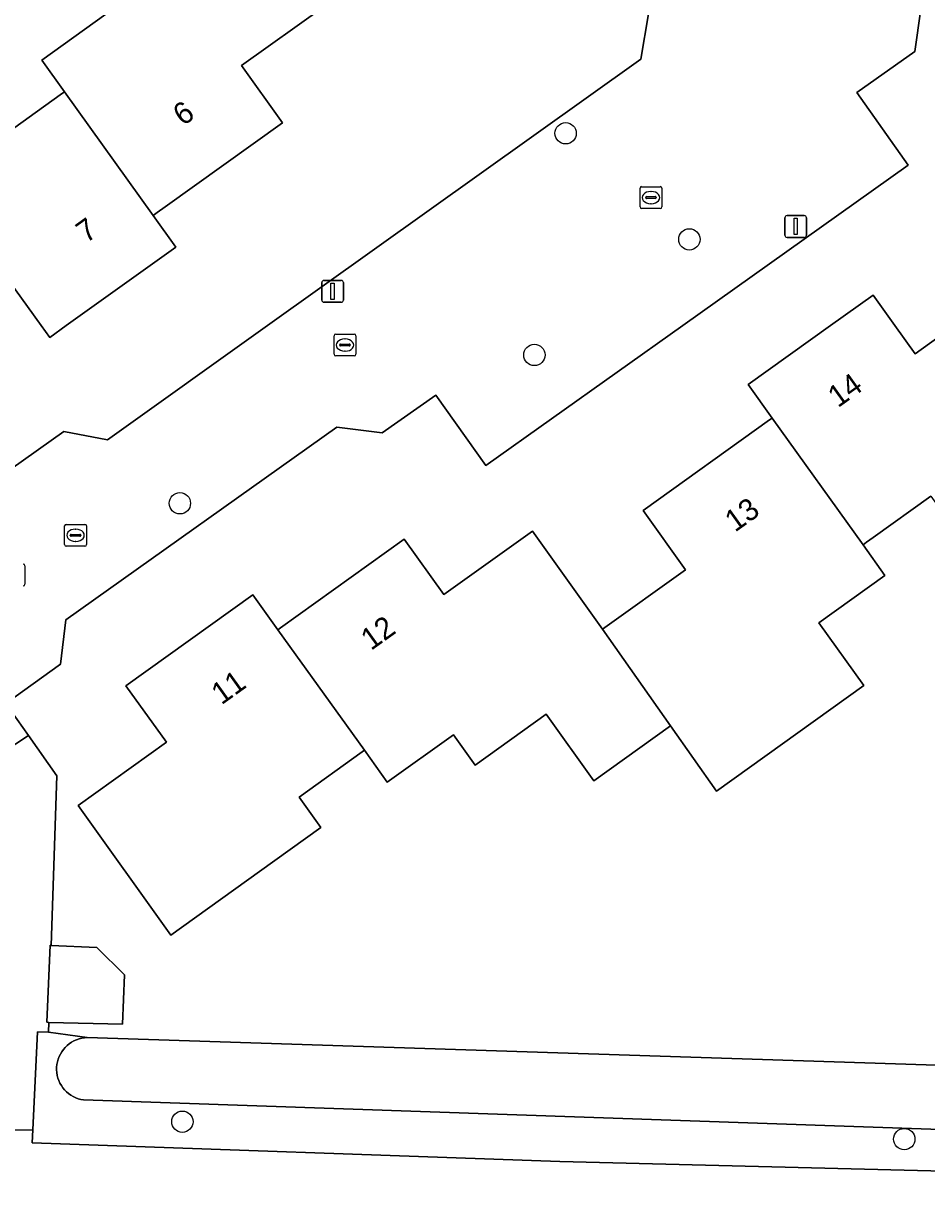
# Model space of a CAD drawing. Extents: x 158455 to 159797, y 387218 to 388672.
# Drawn here: x 159236.8 to 159278.2, y 387710.4 to 387763.8 of the extents above; entities that cross this region are included whole.
import ezdxf

# ---------------------------------------------------------------- set-up
doc = ezdxf.new("R2010")
doc.units = 0
for name, color, linetype in [('IMGEO_Boom', 7, 'Continuous'), ('IMGEO_Erf', 7, 'Continuous'), ('IMGEO_Groenvoorziening', 7, 'Continuous'), ('IMGEO_Kolk', 7, 'Continuous'), ('IMGEO_Lichtmast', 7, 'Continuous'), ('IMGEO_Pand', 7, 'Continuous'), ('IMGEO_Pand_nummerreeks', 7, 'Continuous'), ('IMGEO_Rijbaan_lokaal_open', 7, 'Continuous'), ('IMGEO_Rioolput', 7, 'Continuous'), ('IMGEO_Voetpad_halfverhard', 7, 'Continuous'), ('IMGEO_Voetpad_open', 7, 'Continuous'), ('IMGEO_Waterloop', 7, 'Continuous')]:
    doc.layers.add(name, color=color, linetype=linetype)

msp = doc.modelspace()

# ---------------------------------------------------------------- linework, layer by layer
at = {"layer": 'IMGEO_Boom'}
for centre in [(159261.608, 387758.813), (159267.278, 387753.948), (159260.177, 387748.653), (159243.927, 387741.855), (159244.041, 387713.516), (159277.129, 387712.716)]:
    msp.add_circle(centre, 0.489, dxfattribs=at)
at = {"layer": 'IMGEO_Erf'}
for points in [[(159219.866, 387766.077), (159225.4, 387758.477), (159225.842, 387757.87), (159227.788, 387755.197), (159234.513, 387760.012), (159235.582, 387758.518), (159238.444, 387760.567), (159238.638, 387760.706), (159237.594, 387762.164), (159240.534, 387764.269)], [(159250.519, 387764.612), (159246.754, 387761.916), (159248.635, 387759.288), (159243.252, 387755.433), (159242.894, 387755.177), (159242.699, 387755.037), (159243.735, 387753.59), (159238.722, 387750), (159237.962, 387749.456), (159237.572, 387750), (159236.047, 387752.13), (159235.872, 387752.374), (159234.896, 387751.676), (159235.071, 387751.431), (159233.071, 387750), (159232.039, 387749.261), (159236.184, 387743.412), (159238.603, 387745.147), (159240.605, 387744.76), (159247.948, 387750), (159265.053, 387762.206), (159265.409, 387764.288)], [(159277.893, 387764.497), (159277.605, 387762.555), (159274.948, 387760.678), (159277.299, 387757.343), (159266.972, 387750), (159257.945, 387743.581), (159255.655, 387746.817), (159253.197, 387745.09), (159251.126, 387745.348), (159238.707, 387736.519), (159238.451, 387734.477), (159235.953, 387732.682), (159236.986, 387731.212), (159238.284, 387729.366), (159238.03, 387721.596), (159240.126, 387721.505), (159241.394, 387720.245), (159241.296, 387717.992), (159237.915, 387718.068), (159237.9, 387717.615), (159239.681, 387717.367), (159366.763, 387713.237)], [(159278.344, 387742.177), (159275.701, 387740.283), (159275.402, 387740.069), (159275.24, 387739.953), (159276.243, 387738.553), (159273.209, 387736.38), (159275.27, 387733.502), (159268.522, 387728.668), (159266.418, 387731.657), (159262.899, 387729.137), (159260.716, 387732.185), (159257.468, 387729.858), (159256.47, 387731.25), (159253.434, 387729.075), (159252.386, 387730.534), (159252.287, 387730.463), (159249.394, 387728.391), (159250.394, 387726.995), (159247.581, 387724.981), (159243.516, 387722.069), (159239.265, 387728.004), (159243.313, 387730.904), (159241.458, 387733.492), (159247.273, 387737.658), (159248.419, 387736.061), (159248.541, 387736.148), (159254.213, 387740.211), (159256.029, 387737.676), (159260.082, 387740.579), (159263.303, 387736.081), (159267.105, 387738.805), (159265.159, 387741.522), (159270.956, 387745.675), (159271.077, 387745.762), (159269.977, 387747.297), (159273.75, 387750), (159275.697, 387751.395), (159276.697, 387750), (159277.626, 387748.703), (159279.437, 387750)]]:
    msp.add_lwpolyline(points, dxfattribs=at)
at = {"layer": 'IMGEO_Groenvoorziening'}
msp.add_lwpolyline([(159368.812, 387710.04), (159239.517, 387714.512), (159239.393, 387714.535), (159239.272, 387714.568), (159239.154, 387714.612), (159239.041, 387714.666), (159238.932, 387714.73), (159238.83, 387714.803), (159238.734, 387714.884), (159238.646, 387714.974), (159238.566, 387715.071), (159238.495, 387715.175), (159238.433, 387715.285), (159238.382, 387715.399), (159238.34, 387715.518), (159238.309, 387715.64), (159238.289, 387715.764), (159238.279, 387715.889), (159238.281, 387716.015), (159238.294, 387716.14), (159238.317, 387716.264), (159238.352, 387716.385), (159238.397, 387716.502), (159238.451, 387716.616), (159238.516, 387716.723), (159238.59, 387716.825), (159238.672, 387716.92), (159238.763, 387717.008), (159238.861, 387717.087), (159238.965, 387717.157), (159239.075, 387717.218), (159239.19, 387717.269), (159239.309, 387717.309), (159239.431, 387717.339), (159239.556, 387717.359), (159239.681, 387717.367), (159237.9, 387717.615), (159237.4, 387717.632), (159237.189, 387713.141), (159237.161, 387712.542), (159261.348, 387711.686), (159337.222, 387709.784)], dxfattribs=at)
at = {"layer": 'IMGEO_Kolk'}
for p, q in [((159265.017, 387755.438), (159265.017, 387756.29)), ((159265.092, 387756.364), (159265.944, 387756.364)), ((159265.505, 387756.144), (159265.53, 387756.144)), ((159266.018, 387756.29), (159266.018, 387755.438)), ((159265.276, 387755.858), (159265.276, 387755.87)), ((159265.714, 387755.821), (159265.316, 387755.821)), ((159265.319, 387755.907), (159265.717, 387755.907)), ((159265.528, 387755.584), (159265.503, 387755.584)), ((159265.76, 387755.87), (159265.76, 387755.858)), ((159265.944, 387755.364), (159265.092, 387755.364)), ((159251.068, 387749.607), (159251.92, 387749.607)), ((159250.993, 387748.681), (159250.993, 387749.533)), ((159251.252, 387749.101), (159251.252, 387749.113)), ((159251.69, 387749.064), (159251.292, 387749.064)), ((159251.295, 387749.15), (159251.693, 387749.15)), ((159251.481, 387749.387), (159251.506, 387749.387)), ((159251.736, 387749.113), (159251.736, 387749.101)), ((159251.994, 387749.533), (159251.994, 387748.681)), ((159251.92, 387748.607), (159251.068, 387748.607)), ((159251.504, 387748.827), (159251.479, 387748.827)), ((159238.647, 387739.962), (159238.647, 387740.814)), ((159238.722, 387740.888), (159239.574, 387740.888)), ((159239.135, 387740.668), (159239.16, 387740.668)), ((159239.648, 387740.814), (159239.648, 387739.962)), ((159238.906, 387740.382), (159238.906, 387740.394)), ((159239.344, 387740.345), (159238.946, 387740.345)), ((159238.949, 387740.431), (159239.347, 387740.431)), ((159239.158, 387740.108), (159239.133, 387740.108)), ((159239.39, 387740.394), (159239.39, 387740.382)), ((159239.574, 387739.888), (159238.722, 387739.888))]:
    msp.add_line(p, q, dxfattribs=at)
for points in [[(159265.017, 387755.438), (159265.017, 387756.29)], [(159265.092, 387756.364), (159265.944, 387756.364)], [(159266.018, 387756.29), (159266.018, 387755.438)], [(159265.944, 387755.364), (159265.092, 387755.364)], [(159251.068, 387749.607), (159251.92, 387749.607)], [(159250.993, 387748.681), (159250.993, 387749.533)], [(159251.994, 387749.533), (159251.994, 387748.681)], [(159251.92, 387748.607), (159251.068, 387748.607)], [(159238.647, 387739.962), (159238.647, 387740.814)], [(159238.722, 387740.888), (159239.574, 387740.888)], [(159239.648, 387740.814), (159239.648, 387739.962)], [(159239.574, 387739.888), (159238.722, 387739.888)]]:
    msp.add_lwpolyline(points, dxfattribs=at)
for centre, radius, start, end in [((159265.094, 387756.288), 0.0765, 91.552, 178.448), ((159265.094, 387756.288), 0.0765, 91.552, 178.448), ((159265.942, 387756.288), 0.0765, 1.552, 88.448), ((159265.942, 387756.288), 0.0765, 1.552, 88.448), ((159265.094, 387755.44), 0.0765, 181.552, 268.448), ((159265.094, 387755.44), 0.0765, 181.552, 268.448), ((159265.316, 387755.867), 0.0403, 85.8775, 175.7526), ((159265.313, 387755.857), 0.0366, 178.938, 274.7102), ((159265.717, 387755.864), 0.043, 264.8664, 352.4533), ((159265.721, 387755.869), 0.0386, 1.7309, 96.639), ((159265.942, 387755.44), 0.0765, 271.552, 358.448), ((159265.942, 387755.44), 0.0765, 271.552, 358.448), ((159251.07, 387749.531), 0.0765, 91.552, 178.448), ((159251.07, 387749.531), 0.0765, 91.552, 178.448), ((159251.918, 387749.531), 0.0765, 1.552, 88.448), ((159251.918, 387749.531), 0.0765, 1.552, 88.448), ((159251.292, 387749.11), 0.0403, 85.8775, 175.7526), ((159251.289, 387749.1), 0.0366, 178.938, 274.7102), ((159251.693, 387749.107), 0.043, 264.8664, 352.4533), ((159251.697, 387749.112), 0.0386, 1.7309, 96.639), ((159251.07, 387748.683), 0.0765, 181.552, 268.448), ((159251.07, 387748.683), 0.0765, 181.552, 268.448), ((159251.918, 387748.683), 0.0765, 271.552, 358.448), ((159251.918, 387748.683), 0.0765, 271.552, 358.448), ((159238.724, 387740.812), 0.0765, 91.552, 178.448), ((159238.724, 387740.812), 0.0765, 91.552, 178.448), ((159239.572, 387740.812), 0.0765, 1.552, 88.448), ((159239.572, 387740.812), 0.0765, 1.552, 88.448), ((159238.724, 387739.964), 0.0765, 181.552, 268.448), ((159238.724, 387739.964), 0.0765, 181.552, 268.448), ((159238.946, 387740.391), 0.0403, 85.8775, 175.7526), ((159238.943, 387740.381), 0.0366, 178.938, 274.7102), ((159239.347, 387740.388), 0.043, 264.8664, 352.4533), ((159239.351, 387740.393), 0.0386, 1.7309, 96.639), ((159239.572, 387739.964), 0.0765, 271.552, 358.448), ((159239.572, 387739.964), 0.0765, 271.552, 358.448)]:
    msp.add_arc(centre, radius, start, end, dxfattribs=at)
for centre, major_axis, ratio, start_param, end_param in [((159265.504, 387755.864), (-0.387, 0.002), 0.722429, 4.712389, 7.853982), ((159265.529, 387755.864), (-0.39, 0.002), 0.717154, 1.570796, 4.712389), ((159251.48, 387749.107), (-0.387, 0.002), 0.722429, 4.712389, 7.853982), ((159251.505, 387749.107), (-0.39, 0.002), 0.717154, 1.570796, 4.712389), ((159239.134, 387740.388), (-0.387, 0.002), 0.722429, 4.712389, 7.853982), ((159239.159, 387740.388), (-0.39, 0.002), 0.717154, 1.570796, 4.712389)]:
    msp.add_ellipse(centre, major_axis=major_axis, ratio=ratio, start_param=start_param, end_param=end_param, dxfattribs=at)
at = {"layer": 'IMGEO_Lichtmast'}
for p, q in [((159271.654, 387754.142), (159271.654, 387754.942)), ((159271.654, 387754.942), (159271.654, 387754.142)), ((159271.754, 387755.042), (159272.544, 387755.042)), ((159272.544, 387755.042), (159271.754, 387755.042)), ((159272.644, 387754.942), (159272.644, 387754.142)), ((159272.644, 387754.142), (159272.644, 387754.942)), ((159272.544, 387754.042), (159271.754, 387754.042)), ((159271.754, 387754.042), (159272.544, 387754.042)), ((159250.431, 387751.168), (159250.431, 387751.968)), ((159250.431, 387751.968), (159250.431, 387751.168)), ((159250.531, 387752.068), (159251.321, 387752.068)), ((159251.321, 387752.068), (159250.531, 387752.068)), ((159251.421, 387751.968), (159251.421, 387751.168)), ((159251.421, 387751.168), (159251.421, 387751.968)), ((159251.321, 387751.068), (159250.531, 387751.068)), ((159250.531, 387751.068), (159251.321, 387751.068))]:
    msp.add_line(p, q, dxfattribs=at)
for points in [[(159272.074, 387754.917), (159272.224, 387754.917), (159272.224, 387754.167), (159272.074, 387754.167), (159272.074, 387754.917)], [(159250.851, 387751.943), (159251.001, 387751.943), (159251.001, 387751.193), (159250.851, 387751.193), (159250.851, 387751.943)]]:
    msp.add_lwpolyline(points, dxfattribs=at)
for centre, start, end in [((159271.754, 387754.942), 90, 180), ((159271.754, 387754.942), 90, 180), ((159272.544, 387754.942), 0, 90), ((159272.544, 387754.942), 360, 90), ((159271.754, 387754.142), 180, 270), ((159271.754, 387754.142), 180, 270), ((159272.544, 387754.142), 270, 0), ((159272.544, 387754.142), 270, 0), ((159250.531, 387751.968), 90, 180), ((159250.531, 387751.968), 90, 180), ((159251.321, 387751.968), 0, 90), ((159251.321, 387751.968), 360, 90), ((159250.531, 387751.168), 180, 270), ((159250.531, 387751.168), 180, 270), ((159251.321, 387751.168), 270, 0), ((159251.321, 387751.168), 270, 0)]:
    msp.add_arc(centre, 0.1, start, end, dxfattribs=at)
at = {"layer": 'IMGEO_Pand'}
for points in [[(159250.519, 387764.612), (159246.217, 387770.619), (159243.702, 387774.131), (159240.092, 387771.546), (159242.607, 387768.034), (159239.455, 387765.777), (159240.534, 387764.269), (159237.594, 387762.164), (159238.638, 387760.706), (159242.699, 387755.037), (159242.894, 387755.177), (159243.252, 387755.433), (159248.635, 387759.288), (159246.754, 387761.916)], [(159238.638, 387760.706), (159238.444, 387760.567), (159235.582, 387758.518), (159234.513, 387760.012), (159227.788, 387755.197), (159231.51, 387750), (159232.039, 387749.261), (159233.071, 387750), (159235.071, 387751.431), (159234.896, 387751.676), (159235.872, 387752.374), (159236.047, 387752.13), (159237.572, 387750), (159237.962, 387749.456), (159238.722, 387750), (159243.735, 387753.59), (159242.699, 387755.037)], [(159282.735, 387750), (159281.618, 387751.562), (159281.499, 387751.477), (159279.437, 387750), (159277.626, 387748.703), (159276.697, 387750), (159275.697, 387751.395), (159273.75, 387750), (159269.977, 387747.297), (159271.077, 387745.762), (159275.24, 387739.953), (159275.402, 387740.069), (159275.701, 387740.283), (159278.344, 387742.177), (159279.38, 387740.73), (159285.986, 387745.462)], [(159276.243, 387738.553), (159275.24, 387739.953), (159271.077, 387745.762), (159270.956, 387745.675), (159265.159, 387741.522), (159267.105, 387738.805), (159263.303, 387736.081), (159266.418, 387731.657), (159268.522, 387728.668), (159275.27, 387733.502), (159273.209, 387736.38)], [(159263.303, 387736.081), (159260.082, 387740.579), (159256.029, 387737.676), (159254.213, 387740.211), (159248.541, 387736.148), (159248.419, 387736.061), (159252.386, 387730.534), (159253.434, 387729.075), (159256.47, 387731.25), (159257.468, 387729.858), (159260.716, 387732.185), (159262.899, 387729.137), (159266.418, 387731.657)], [(159252.287, 387730.463), (159252.386, 387730.534), (159248.419, 387736.061), (159247.273, 387737.658), (159241.458, 387733.492), (159243.313, 387730.904), (159239.265, 387728.004), (159243.516, 387722.069), (159247.581, 387724.981), (159250.394, 387726.995), (159249.394, 387728.391)], [(159238.03, 387721.596), (159237.985, 387721.598), (159237.832, 387718.07), (159237.915, 387718.068), (159241.296, 387717.992), (159241.394, 387720.245), (159240.126, 387721.505)]]:
    msp.add_lwpolyline(points, close=True, dxfattribs=at)
at = {"layer": 'IMGEO_Rijbaan_lokaal_open'}
for points in [[(159235.227, 387730.066), (159236.986, 387731.212), (159235.953, 387732.682), (159238.451, 387734.477), (159238.707, 387736.519), (159251.126, 387745.348), (159253.197, 387745.09), (159255.655, 387746.817), (159257.945, 387743.581), (159266.972, 387750), (159277.299, 387757.343), (159274.948, 387760.678), (159277.605, 387762.555), (159277.893, 387764.497)], [(159265.409, 387764.288), (159265.053, 387762.206), (159247.948, 387750), (159240.605, 387744.76), (159238.603, 387745.147), (159236.184, 387743.412)]]:
    msp.add_lwpolyline(points, dxfattribs=at)
at = {"layer": 'IMGEO_Rioolput'}
msp.add_line((159236.826, 387738.993), (159236.826, 387738.141), dxfattribs=at)
msp.add_lwpolyline([(159236.826, 387738.993), (159236.826, 387738.141)], dxfattribs=at)
for centre, start, end in [((159236.75, 387738.991), 1.552, 88.448), ((159236.75, 387738.991), 1.552, 88.448), ((159236.75, 387738.143), 271.552, 358.448), ((159236.75, 387738.143), 271.552, 358.448)]:
    msp.add_arc(centre, 0.0765, start, end, dxfattribs=at)
at = {"layer": 'IMGEO_Voetpad_halfverhard'}
msp.add_lwpolyline([(159440.368, 387706.497), (159440.403, 387707.122), (159439.155, 387707.164), (159439.115, 387706.535), (159433.346, 387706.713), (159386.156, 387708.167), (159372.279, 387708.595), (159372.194, 387709.441), (159371.015, 387709.344), (159371.1, 387708.633), (159337.222, 387709.784), (159261.348, 387711.686), (159237.161, 387712.542), (159237.189, 387713.141), (159235.969, 387713.133), (159235.947, 387712.585), (159217.158, 387713.181), (159215.858, 387713.235), (159215.088, 387713.348), (159209.072, 387716.044), (159214.062, 387706.489), (159214.378, 387707.16), (159215.755, 387708.691), (159216.346, 387709.347)], dxfattribs=at)
at = {"layer": 'IMGEO_Voetpad_open'}
msp.add_lwpolyline([(159238.284, 387729.366), (159236.986, 387731.212), (159235.227, 387730.066), (159236.179, 387728.753), (159235.73, 387717.691), (159236.15, 387717.664), (159235.969, 387713.133), (159237.189, 387713.141), (159237.4, 387717.632), (159237.9, 387717.615), (159237.915, 387718.068), (159237.832, 387718.07), (159237.985, 387721.598), (159238.03, 387721.596)], close=True, dxfattribs=at)
at = {"layer": 'IMGEO_Waterloop'}
msp.add_lwpolyline([(159366.763, 387713.237), (159239.681, 387717.367), (159239.556, 387717.359), (159239.431, 387717.339), (159239.309, 387717.309), (159239.19, 387717.269), (159239.075, 387717.218), (159238.965, 387717.157), (159238.861, 387717.087), (159238.763, 387717.008), (159238.672, 387716.92), (159238.59, 387716.825), (159238.516, 387716.723), (159238.451, 387716.616), (159238.397, 387716.502), (159238.352, 387716.385), (159238.317, 387716.264), (159238.294, 387716.14), (159238.281, 387716.015), (159238.279, 387715.889), (159238.289, 387715.764), (159238.309, 387715.64), (159238.34, 387715.518), (159238.382, 387715.399), (159238.433, 387715.285), (159238.495, 387715.175), (159238.566, 387715.071), (159238.646, 387714.974), (159238.734, 387714.884), (159238.83, 387714.803), (159238.932, 387714.73), (159239.041, 387714.666), (159239.154, 387714.612), (159239.272, 387714.568), (159239.393, 387714.535), (159239.517, 387714.512), (159368.812, 387710.04)], dxfattribs=at)

# ---------------------------------------------------------------- texts
at = {"layer": 'IMGEO_Pand_nummerreeks'}
for s, rotation, p in [('6', 35.6036, (159244.074, 387759.12)), ('7', 35.6036, (159239.636, 387753.752)), ('14', 35.6151, (159274.089, 387746.208)), ('13', 35.6208, (159269.37, 387740.504)), ('12', 35.6151, (159252.687, 387735.083)), ('11', 35.6151, (159245.833, 387732.591))]:
    msp.add_text(s, height=1, rotation=rotation, dxfattribs=at).set_placement(p)

doc.saveas('drawing.dxf')
